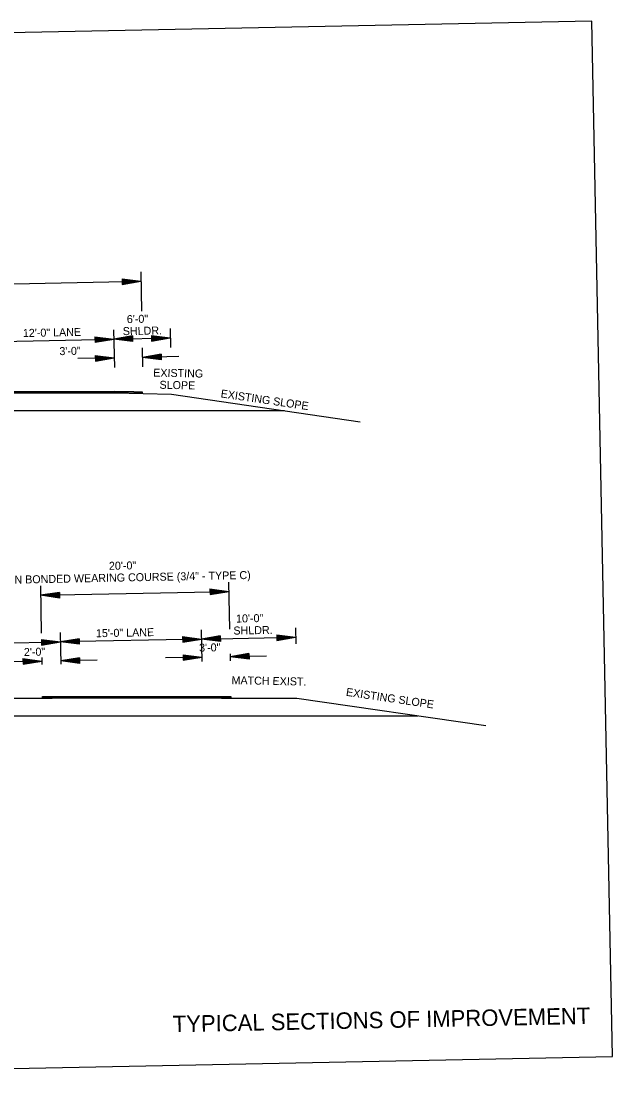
# Model space of a CAD drawing. Extents: x 174 to 869, y -36 to 177.
# Drawn here: x 457.2 to 520.1, y 57.1 to 170.5 of the extents above; entities that cross this region are included whole.
import ezdxf

# ---------------------------------------------------------------- set-up
doc = ezdxf.new("R2010")
doc.units = 0
for name, color, linetype in [('DSN_DRFT_Common-Annotations', 7, 'Continuous'), ('DSN_DRFT_Common-Line', 7, 'Continuous'), ('DSN_DRFT_Dimension', 7, 'Continuous'), ('SHET_Border-Text', 7, 'Continuous')]:
    doc.layers.add(name, color=color, linetype=linetype)

msp = doc.modelspace()

# ---------------------------------------------------------------- linework, layer by layer
at = {"layer": 'DSN_DRFT_Common-Line'}
for p, q in [((469.93, 143.86), (470.01, 139.68)), ((467.05, 137.71), (467.13, 133.71)), ((473.05, 137.83), (473.09, 135.83)), ((470.09, 135.77), (470.13, 133.77)), ((431.17, 131.16), (467.18, 131.16)), ((431.18, 130.99), (467.18, 130.99)), ((467.18, 130.99), (473.19, 130.87)), ((470.08, 131.1), (470.07, 130.94)), ((473.19, 130.87), (493.25, 127.94)), ((431.21, 129.12), (485.19, 129.12)), ((459.27, 110.51), (459.37, 105.49)), ((479.26, 110.91), (479.36, 105.89)), ((461.37, 105.53), (461.43, 102.17)), ((476.36, 105.83), (476.43, 102.47)), ((486.36, 106.05), (486.39, 104.35)), ((479.42, 103.29), (479.43, 102.53)), ((459.42, 102.89), (459.43, 102.13)), ((439.5, 98.57), (460.51, 98.57)), ((478.51, 98.58), (486.51, 98.58)), ((486.51, 98.58), (506.57, 95.65)), ((412.53, 96.7), (499.37, 96.7))]:
    msp.add_line(p, q, dxfattribs=at)
for points in [[(347.89, 167.07), (350.09, 57.09), (520.05, 60.49), (517.85, 170.47)], [(467.18, 130.99), (431.18, 130.99), (419.18, 130.51), (416.19, 130.39), (416.18, 130.56), (419.18, 130.68), (431.17, 131.16), (467.18, 131.16), (470.08, 131.1), (470.07, 130.94)], [(479.51, 98.58), (459.5, 98.57), (459.5, 98.57), (459.5, 98.57), (459.5, 98.74), (459.5, 98.74), (459.5, 98.74), (479.51, 98.75), (479.51, 98.75), (479.51, 98.58)]]:
    msp.add_lwpolyline(points, close=True, dxfattribs=at)
msp.add_lwpolyline([(469.18, 131.12), (467.18, 131.16), (469.18, 131.12), (470.08, 131.1)], dxfattribs=at)
at = {"layer": 'DSN_DRFT_Dimension'}
for p, q in [((415.96, 141.78), (469.95, 142.86)), ((467.94, 143.12), (469.95, 142.86)), ((467.94, 143.12), (467.95, 142.52)), ((467.94, 143.07), (469.61, 142.85)), ((467.94, 143.02), (469.27, 142.84)), ((467.94, 142.97), (468.94, 142.84)), ((467.95, 142.91), (468.6, 142.83)), ((467.95, 142.52), (469.95, 142.86)), ((467.95, 142.86), (468.26, 142.82)), ((467.95, 142.57), (469.61, 142.85)), ((467.95, 142.62), (469.27, 142.84)), ((467.95, 142.67), (468.94, 142.84)), ((467.95, 142.72), (468.6, 142.83)), ((467.95, 142.77), (468.26, 142.82)), ((455.07, 136.47), (467.07, 136.71)), ((465.06, 136.97), (467.07, 136.71)), ((465.06, 136.97), (465.08, 136.37)), ((465.06, 136.92), (466.74, 136.71)), ((465.07, 136.87), (466.39, 136.7)), ((465.07, 136.82), (466.06, 136.69)), ((465.07, 136.77), (465.72, 136.69)), ((465.07, 136.72), (465.39, 136.68)), ((465.07, 136.42), (466.74, 136.71)), ((465.07, 136.47), (466.39, 136.7)), ((465.07, 136.58), (465.72, 136.69)), ((465.07, 136.52), (466.06, 136.69)), ((465.07, 136.63), (465.39, 136.68)), ((465.08, 136.37), (467.07, 136.71)), ((469.06, 137.05), (467.07, 136.71)), ((467.07, 136.71), (473.07, 136.83)), ((469.07, 136.45), (467.07, 136.71)), ((469.06, 137), (467.4, 136.72)), ((469.07, 136.5), (467.4, 136.72)), ((469.06, 136.95), (467.75, 136.73)), ((469.07, 136.55), (467.75, 136.73)), ((469.07, 136.9), (468.08, 136.73)), ((469.07, 136.6), (468.08, 136.73)), ((469.07, 136.85), (468.42, 136.74)), ((469.07, 136.66), (468.42, 136.74)), ((469.07, 136.8), (468.75, 136.75)), ((469.07, 136.71), (468.75, 136.75)), ((469.06, 137.05), (469.07, 136.45)), ((471.06, 137.09), (473.07, 136.83)), ((471.06, 137.09), (471.07, 136.49)), ((471.06, 137.04), (472.73, 136.83)), ((471.06, 136.99), (472.39, 136.82)), ((471.07, 136.94), (472.06, 136.81)), ((471.07, 136.89), (471.72, 136.81)), ((471.07, 136.84), (471.38, 136.8)), ((471.07, 136.49), (473.07, 136.83)), ((471.07, 136.54), (472.73, 136.83)), ((471.07, 136.59), (472.39, 136.82)), ((471.07, 136.7), (471.72, 136.81)), ((471.07, 136.64), (472.06, 136.81)), ((471.07, 136.75), (471.38, 136.8)), ((465.1, 134.97), (467.11, 134.71)), ((465.1, 134.97), (465.12, 134.37)), ((465.1, 134.92), (466.78, 134.71)), ((472.1, 135.11), (470.11, 134.77)), ((472.1, 135.06), (470.44, 134.78)), ((472.1, 135.01), (470.79, 134.79)), ((472.11, 134.96), (471.12, 134.79)), ((472.1, 135.11), (472.11, 134.51)), ((467.11, 134.73), (463.24, 134.66)), ((465.11, 134.87), (466.43, 134.7)), ((465.11, 134.82), (466.1, 134.69)), ((465.11, 134.77), (465.76, 134.69)), ((465.11, 134.72), (465.43, 134.68)), ((465.11, 134.42), (466.78, 134.71)), ((465.11, 134.47), (466.43, 134.7)), ((465.11, 134.58), (465.76, 134.69)), ((465.11, 134.52), (466.1, 134.69)), ((465.11, 134.63), (465.43, 134.68)), ((465.12, 134.37), (467.11, 134.71)), ((473.97, 134.85), (470.11, 134.77)), ((472.11, 134.51), (470.11, 134.77)), ((472.11, 134.56), (470.44, 134.78)), ((472.11, 134.61), (470.79, 134.79)), ((472.11, 134.66), (471.12, 134.79)), ((472.11, 134.91), (471.46, 134.8)), ((472.11, 134.72), (471.46, 134.8)), ((472.11, 134.86), (471.79, 134.81)), ((472.11, 134.77), (471.79, 134.81)), ((477.28, 110.17), (479.28, 109.91)), ((477.28, 110.17), (477.29, 109.57)), ((477.28, 110.12), (478.95, 109.9)), ((477.28, 110.07), (478.61, 109.9)), ((477.28, 110.02), (478.27, 109.89)), ((459.29, 109.51), (479.28, 109.91)), ((461.29, 109.81), (459.29, 109.51)), ((461.29, 109.21), (459.29, 109.51)), ((461.29, 109.76), (459.62, 109.51)), ((461.29, 109.26), (459.62, 109.51)), ((461.29, 109.71), (459.96, 109.51)), ((461.29, 109.31), (459.96, 109.51)), ((461.29, 109.66), (460.3, 109.51)), ((461.29, 109.36), (460.3, 109.51)), ((461.29, 109.61), (460.64, 109.51)), ((461.29, 109.41), (460.64, 109.51)), ((461.29, 109.56), (460.97, 109.51)), ((461.29, 109.46), (460.97, 109.51)), ((461.29, 109.81), (461.29, 109.21)), ((477.28, 109.97), (477.93, 109.88)), ((477.28, 109.92), (477.6, 109.88)), ((477.28, 109.82), (477.6, 109.88)), ((477.29, 109.57), (479.28, 109.91)), ((477.29, 109.67), (478.61, 109.9)), ((477.29, 109.62), (478.95, 109.9)), ((477.29, 109.72), (478.27, 109.89)), ((477.29, 109.77), (477.93, 109.88)), ((436.39, 104.05), (461.39, 104.55)), ((459.38, 104.81), (461.39, 104.55)), ((459.38, 104.81), (459.39, 104.21)), ((459.38, 104.76), (461.05, 104.55)), ((459.38, 104.71), (460.71, 104.54)), ((459.38, 104.66), (460.37, 104.53)), ((459.38, 104.61), (460.04, 104.53)), ((459.39, 104.56), (459.7, 104.52)), ((459.39, 104.21), (461.39, 104.55)), ((459.39, 104.26), (461.05, 104.55)), ((459.39, 104.31), (460.71, 104.54)), ((459.39, 104.41), (460.04, 104.53)), ((459.39, 104.36), (460.37, 104.53)), ((459.39, 104.47), (459.7, 104.52)), ((463.38, 104.89), (461.39, 104.55)), ((476.38, 104.85), (461.39, 104.55)), ((463.39, 104.29), (461.39, 104.55)), ((463.38, 104.84), (461.72, 104.56)), ((463.39, 104.34), (461.72, 104.56)), ((463.38, 104.79), (462.06, 104.57)), ((463.39, 104.39), (462.06, 104.57)), ((463.38, 104.74), (462.4, 104.57)), ((463.39, 104.44), (462.4, 104.57)), ((463.38, 104.69), (462.74, 104.58)), ((463.39, 104.49), (462.74, 104.58)), ((463.38, 104.64), (463.07, 104.59)), ((463.39, 104.55), (463.07, 104.59)), ((463.38, 104.89), (463.39, 104.29)), ((474.38, 105.11), (476.38, 104.85)), ((474.38, 105.11), (474.39, 104.51)), ((474.38, 105.06), (476.05, 104.85)), ((474.38, 105.01), (475.7, 104.84)), ((474.38, 104.96), (475.37, 104.83)), ((474.38, 104.91), (475.03, 104.83)), ((474.38, 104.86), (474.7, 104.82)), ((474.38, 104.77), (474.7, 104.82)), ((474.39, 104.51), (476.38, 104.85)), ((474.39, 104.56), (476.05, 104.85)), ((474.39, 104.61), (475.7, 104.84)), ((474.39, 104.71), (475.03, 104.83)), ((474.39, 104.66), (475.37, 104.83)), ((478.38, 105.19), (476.38, 104.85)), ((476.38, 104.85), (486.38, 105.05)), ((478.39, 104.59), (476.38, 104.85)), ((478.38, 105.14), (476.72, 104.86)), ((478.39, 104.64), (476.72, 104.86)), ((478.38, 105.09), (477.06, 104.87)), ((478.39, 104.69), (477.06, 104.87)), ((478.38, 105.04), (477.39, 104.87)), ((478.39, 104.74), (477.39, 104.87)), ((478.38, 104.99), (477.73, 104.88)), ((478.38, 104.79), (477.73, 104.88)), ((478.38, 104.94), (478.07, 104.89)), ((478.38, 104.85), (478.07, 104.89)), ((478.38, 105.19), (478.39, 104.59)), ((484.38, 105.31), (486.38, 105.05)), ((484.38, 105.31), (484.39, 104.71)), ((484.38, 105.26), (486.05, 105.05)), ((484.38, 105.21), (485.7, 105.04)), ((484.38, 105.16), (485.37, 105.03)), ((484.38, 105.11), (485.03, 105.03)), ((484.38, 105.06), (484.7, 105.02)), ((484.38, 104.91), (485.03, 105.03)), ((484.38, 104.86), (485.37, 105.03)), ((484.38, 104.97), (484.7, 105.02)), ((484.39, 104.71), (486.38, 105.05)), ((484.39, 104.76), (486.05, 105.05)), ((484.39, 104.81), (485.7, 105.04)), ((474.42, 103.19), (476.42, 102.93)), ((474.42, 103.19), (474.43, 102.59)), ((481.42, 103.31), (479.42, 102.97)), ((481.42, 103.26), (479.76, 102.97)), ((481.42, 103.21), (480.1, 102.98)), ((481.42, 103.31), (481.43, 102.71)), ((459.43, 102.51), (455.56, 102.44)), ((457.42, 102.77), (459.43, 102.51)), ((457.42, 102.77), (457.43, 102.17)), ((457.42, 102.72), (459.09, 102.51)), ((457.42, 102.67), (458.75, 102.5)), ((457.42, 102.62), (458.42, 102.49)), ((457.42, 102.57), (458.08, 102.49)), ((457.43, 102.52), (457.74, 102.48)), ((457.43, 102.17), (459.43, 102.51)), ((457.43, 102.22), (459.09, 102.51)), ((457.43, 102.27), (458.75, 102.5)), ((457.43, 102.37), (458.08, 102.49)), ((457.43, 102.32), (458.42, 102.49)), ((457.43, 102.43), (457.74, 102.48)), ((463.42, 102.87), (461.43, 102.53)), ((465.29, 102.61), (461.43, 102.53)), ((463.43, 102.27), (461.43, 102.53)), ((463.42, 102.82), (461.76, 102.54)), ((463.43, 102.32), (461.76, 102.54)), ((463.42, 102.77), (462.1, 102.55)), ((463.43, 102.37), (462.1, 102.55)), ((463.42, 102.72), (462.44, 102.55)), ((463.43, 102.42), (462.44, 102.55)), ((463.42, 102.67), (462.78, 102.56)), ((463.43, 102.48), (462.78, 102.56)), ((463.42, 102.62), (463.11, 102.57)), ((463.43, 102.53), (463.11, 102.57)), ((463.42, 102.87), (463.43, 102.27)), ((476.42, 102.93), (472.56, 102.85)), ((474.42, 103.14), (476.09, 102.92)), ((474.42, 103.09), (475.74, 102.91)), ((474.42, 103.04), (475.41, 102.91)), ((474.42, 102.98), (475.07, 102.9)), ((474.42, 102.93), (474.74, 102.89)), ((474.42, 102.74), (475.41, 102.91)), ((474.42, 102.79), (475.07, 102.9)), ((474.42, 102.84), (474.74, 102.89)), ((474.43, 102.59), (476.42, 102.93)), ((474.43, 102.64), (476.09, 102.92)), ((474.43, 102.69), (475.74, 102.91)), ((483.29, 103.04), (479.42, 102.97)), ((481.43, 102.71), (479.42, 102.97)), ((481.43, 102.76), (479.76, 102.97)), ((481.43, 102.81), (480.1, 102.98)), ((481.42, 103.16), (480.43, 102.99)), ((481.42, 102.86), (480.43, 102.99)), ((481.42, 103.1), (480.77, 102.99)), ((481.42, 102.91), (480.77, 102.99)), ((481.42, 103.05), (481.11, 103)), ((481.42, 102.96), (481.11, 103))]:
    msp.add_line(p, q, dxfattribs=at)

# ---------------------------------------------------------------- texts
at = {"layer": 'DSN_DRFT_Common-Annotations'}
for s, rotation, p in [('6\'-0" ', 1.1458, (468.46, 138.41)), ('12\'-0" LANE', 1.1458, (457.42, 136.93)), ('SHLDR.', 1.1458, (468.03, 137.13)), (' 3\'-0"', 1.1458, (460.98, 135)), ('EXISTING ', 358.8552, (471.25, 132.73)), ('SLOPE', 358.8552, (471.92, 131.44)), ('EXISTING SLOPE', 351.6838, (478.38, 130.53)), ('20\'-0"', 1.1458, (466.56, 112.2)), ('ULTRATHIN BONDED WEARING COURSE (3/4" - TYPE C)', 1.1458, (450.97, 110.62)), ('10\'-0"', 1.1458, (480.06, 106.6)), ('15\'-0" LANE', 1.1458, (465.18, 105.04)), ('SHLDR.', 1.1458, (479.78, 105.32)), (' 3\'-0"', 1.1458, (475.82, 103.5)), (' 2\'-0"', 1.1458, (457.21, 103.04)), ('MATCH EXIST.', 358.8552, (479.57, 100.06)), ('EXISTING SLOPE', 351.6838, (491.69, 98.83))]:
    msp.add_text(s, height=0.85, rotation=rotation, dxfattribs=at).set_placement(p)
at = {"layer": 'SHET_Border-Text'}
msp.add_text('TYPICAL SECTIONS OF IMPROVEMENT', height=1.75, rotation=1.1458, dxfattribs=at).set_placement((473.35, 63.08))

doc.saveas('drawing.dxf')
